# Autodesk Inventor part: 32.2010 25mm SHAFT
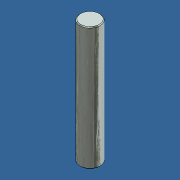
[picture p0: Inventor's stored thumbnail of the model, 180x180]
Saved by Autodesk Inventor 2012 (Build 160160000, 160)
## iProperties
Created: 2016-09
Part Number: 32.2010 25mm SHAFT
Material: Steel
Document SubType Name: Modeling
Designer: Admin
Density: 7.85 g/cm^3
Mass: 488.777 g
Surface Area: 108.617 cm^2
Volume: 62.2645 cm^3
Author: Admin
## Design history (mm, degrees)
sketch "Sketch1"
  geometry: C1 r 12.5 at (0, 0); 1 further point
  constraints: 1 centre point, 1 coincident
  dimensions: "d0" = 25 diameter of C1
extrude "Extrusion1" new body sketch "Sketch1" stored distance "d1" = 152; taper "d2" = 0 deg
chamfer "Chamfer1" distance "d3" = 1; stored, may be unused: second distance "d4" = 2, angle "d5" = 45 deg
body "Solid1"
